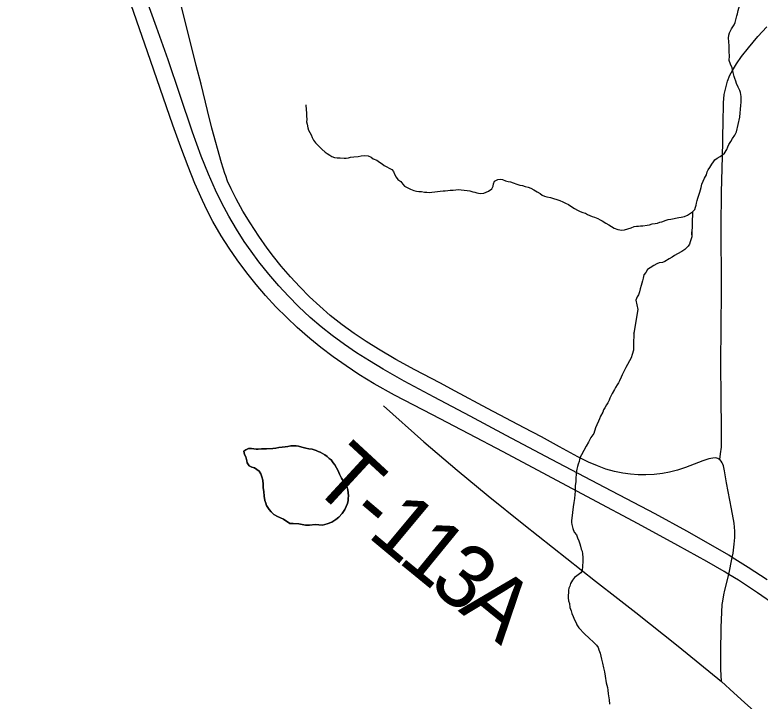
# Model space of a CAD drawing. Extents: x -17 to 88, y -5 to 22.
# Drawn here: x -15.624 to -14.955, y 18.189 to 18.805 of the extents above; entities that cross this region are included whole.
import ezdxf

# ---------------------------------------------------------------- set-up
doc = ezdxf.new("R2010")
doc.units = 0
for name, color, linetype in [('GM_X_County_Road', 7, 'Continuous'), ('GM_X_Minor_Lake', 7, 'Continuous'), ('GM_X_Minor_River', 7, 'Continuous'), ('GM_X_Township_Road', 7, 'Continuous'), ('GM_X_Township_Road_Text', 7, 'Continuous'), ('GM_X_US_Route', 7, 'Continuous')]:
    doc.layers.add(name, color=color, linetype=linetype)

msp = doc.modelspace()

# ---------------------------------------------------------------- linework, layer by layer
at = {"layer": 'GM_X_County_Road'}
for points in [[(-15.43442, 18.66023), (-15.4352, 18.66242), (-15.43811, 18.67197), (-15.44685, 18.7031), (-15.4508, 18.7188), (-15.45633, 18.74239), (-15.46084, 18.75918), (-15.47433, 18.81346), (-15.48111, 18.83865), (-15.48462, 18.85054), (-15.49156, 18.87179), (-15.5076, 18.91951), (-15.5232, 18.9654), (-15.53738, 19.00653), (-15.56505, 19.08573), (-15.5758, 19.11553), (-15.60344, 19.18946), (-15.62132, 19.23584), (-15.6236, 19.24164)], [(-14.99098, 18.40567), (-14.99178, 18.40623), (-14.99268, 18.40666), (-14.99358, 18.40695), (-14.99513, 18.40717), (-14.99738, 18.40713), (-15.00085, 18.40636), (-15.00609, 18.4045), (-15.02183, 18.39852), (-15.02898, 18.39621), (-15.03626, 18.39433), (-15.04243, 18.39321), (-15.04991, 18.3924), (-15.05741, 18.39202), (-15.06429, 18.3921), (-15.07116, 18.39261), (-15.07799, 18.39357), (-15.08535, 18.39508), (-15.0932, 18.39725), (-15.10086, 18.40002), (-15.10887, 18.40356), (-15.11837, 18.40828), (-15.13478, 18.41718), (-15.15112, 18.42614), (-15.16651, 18.43423), (-15.19958, 18.45149), (-15.22856, 18.46716), (-15.24221, 18.47453), (-15.26481, 18.4863), (-15.2817, 18.49561), (-15.29726, 18.50475), (-15.30836, 18.51166), (-15.31923, 18.51893), (-15.32984, 18.52657), (-15.34056, 18.53512), (-15.35, 18.54326), (-15.35911, 18.55176), (-15.3679, 18.56059), (-15.37638, 18.56972), (-15.38456, 18.57912), (-15.39165, 18.58781), (-15.39729, 18.59528), (-15.40471, 18.60605), (-15.41251, 18.61806), (-15.41901, 18.6287), (-15.42513, 18.63956), (-15.42964, 18.64847), (-15.43266, 18.65535), (-15.43442, 18.66023)], [(-14.97983, 18.31801), (-14.97911, 18.32186), (-14.97798, 18.32981), (-14.97754, 18.33593), (-14.9775, 18.34143), (-14.97822, 18.34876), (-14.98053, 18.36155), (-14.98497, 18.38477), (-14.9862, 18.39214), (-14.98681, 18.39578), (-14.98766, 18.39999), (-14.98817, 18.4016), (-14.98871, 18.40279), (-14.98979, 18.40443), (-14.99098, 18.40567)], [(-14.98287, 18.30274), (-14.97983, 18.31801)], [(-14.9894, 18.20667), (-14.99004, 18.21775), (-14.98992, 18.23268), (-14.98961, 18.25505), (-14.98928, 18.26876), (-14.98874, 18.27563), (-14.98835, 18.27874), (-14.98742, 18.2843), (-14.98648, 18.28858), (-14.98287, 18.30274)], [(-14.72434, 17.87666), (-14.7323, 17.88854), (-14.75121, 17.91776), (-14.76907, 17.94467), (-14.78233, 17.96421), (-14.79562, 17.98374), (-14.81879, 18.01757), (-14.83863, 18.04615), (-14.85954, 18.07548), (-14.86774, 18.0864), (-14.87667, 18.09752), (-14.88598, 18.10832), (-14.89776, 18.12109), (-14.90769, 18.13133), (-14.92012, 18.14348), (-14.93733, 18.15962), (-14.9687, 18.18793), (-14.97842, 18.19663), (-14.9894, 18.20667)]]:
    msp.add_lwpolyline(points, dxfattribs=at)
at = {"layer": 'GM_X_Minor_Lake'}
for points in [[(-15.32407, 18.37319), (-15.32483, 18.37851), (-15.32558, 18.38155), (-15.32672, 18.38421), (-15.32862, 18.3861), (-15.33052, 18.38914), (-15.33242, 18.39256), (-15.33356, 18.3956), (-15.33508, 18.39825), (-15.33659, 18.40091), (-15.33811, 18.40281), (-15.33963, 18.40547), (-15.34153, 18.40661), (-15.34343, 18.40851), (-15.34532, 18.41002), (-15.3476, 18.41116), (-15.3495, 18.4123), (-15.3514, 18.41306), (-15.35329, 18.41382), (-15.35671, 18.41496), (-15.35974, 18.41534), (-15.3624, 18.4161), (-15.36619, 18.41686), (-15.36923, 18.41762), (-15.37113, 18.418), (-15.3734, 18.418), (-15.37606, 18.418), (-15.37872, 18.41761), (-15.38099, 18.41723), (-15.38365, 18.41685), (-15.38668, 18.41647), (-15.38934, 18.4161), (-15.392, 18.41571), (-15.39769, 18.41533), (-15.40224, 18.41533), (-15.40527, 18.41495), (-15.40717, 18.41495), (-15.40907, 18.41533), (-15.41135, 18.41571), (-15.414, 18.41571), (-15.41628, 18.41457), (-15.41818, 18.41343)], [(-15.41818, 18.41343), (-15.41628, 18.41457), (-15.414, 18.41571), (-15.41135, 18.41571), (-15.40907, 18.41533), (-15.40717, 18.41495), (-15.40527, 18.41495), (-15.40224, 18.41533), (-15.39769, 18.41533), (-15.392, 18.41571), (-15.38934, 18.4161), (-15.38668, 18.41647), (-15.38365, 18.41685), (-15.38099, 18.41723), (-15.37872, 18.41761), (-15.37606, 18.418), (-15.3734, 18.418), (-15.37113, 18.418), (-15.36923, 18.41762), (-15.36619, 18.41686), (-15.3624, 18.4161), (-15.35974, 18.41534), (-15.35671, 18.41496), (-15.35329, 18.41382), (-15.3514, 18.41306), (-15.3495, 18.4123), (-15.3476, 18.41116), (-15.34532, 18.41002), (-15.34343, 18.40851), (-15.34153, 18.40661), (-15.33963, 18.40547), (-15.33811, 18.40281), (-15.33659, 18.40091), (-15.33508, 18.39825), (-15.33356, 18.3956), (-15.33242, 18.39256), (-15.33052, 18.38914), (-15.32862, 18.3861), (-15.32672, 18.38421), (-15.32558, 18.38155), (-15.32483, 18.37851), (-15.32407, 18.37319), (-15.32444, 18.37091), (-15.32444, 18.36902), (-15.3252, 18.36636), (-15.32634, 18.3637), (-15.32748, 18.36104), (-15.32975, 18.35725), (-15.33279, 18.35421), (-15.33544, 18.35193), (-15.33924, 18.34965), (-15.34341, 18.34813), (-15.34758, 18.34699), (-15.35403, 18.34737), (-15.35934, 18.34699), (-15.36276, 18.34699), (-15.36883, 18.34813), (-15.37376, 18.3485), (-15.3768, 18.3485), (-15.38249, 18.3523), (-15.3878, 18.35458), (-15.39122, 18.35648), (-15.3935, 18.35875), (-15.3954, 18.36103), (-15.39767, 18.36445), (-15.39843, 18.36673), (-15.39919, 18.369), (-15.39995, 18.3728), (-15.40033, 18.37698), (-15.40071, 18.3804), (-15.40071, 18.38343), (-15.40109, 18.38723), (-15.40185, 18.39027), (-15.40299, 18.39293), (-15.40451, 18.39521), (-15.40869, 18.39824), (-15.41096, 18.399), (-15.41324, 18.40014), (-15.41514, 18.4028), (-15.41552, 18.4047), (-15.41628, 18.40812), (-15.41742, 18.41039), (-15.41818, 18.41343)], [(-15.41818, 18.41343), (-15.41742, 18.41039), (-15.41628, 18.40812), (-15.41552, 18.4047), (-15.41514, 18.4028), (-15.41324, 18.40014), (-15.41096, 18.399), (-15.40869, 18.39824), (-15.40451, 18.39521), (-15.40299, 18.39293), (-15.40185, 18.39027), (-15.40109, 18.38723), (-15.40071, 18.38343), (-15.40071, 18.3804), (-15.40033, 18.37698), (-15.39995, 18.3728), (-15.39919, 18.369), (-15.39843, 18.36673), (-15.39767, 18.36445), (-15.3954, 18.36103), (-15.3935, 18.35875), (-15.39122, 18.35648), (-15.3878, 18.35458), (-15.38249, 18.3523), (-15.3768, 18.3485), (-15.37376, 18.3485), (-15.36883, 18.34813), (-15.36276, 18.34699), (-15.35934, 18.34699), (-15.35403, 18.34737), (-15.34758, 18.34699), (-15.34341, 18.34813), (-15.33924, 18.34965), (-15.33544, 18.35193), (-15.33279, 18.35421), (-15.32975, 18.35725), (-15.32748, 18.36104), (-15.32634, 18.3637), (-15.3252, 18.36636), (-15.32444, 18.36902), (-15.32444, 18.37091), (-15.32407, 18.37319)]]:
    msp.add_lwpolyline(points, dxfattribs=at)
at = {"layer": 'GM_X_Minor_River'}
for points in [[(-14.9828, 18.78637), (-14.98238, 18.78864), (-14.98041, 18.79203), (-14.97924, 18.7939), (-14.97806, 18.79578), (-14.97727, 18.79767), (-14.97644, 18.80145), (-14.97563, 18.80371), (-14.97522, 18.8056), (-14.9744, 18.80862), (-14.97399, 18.81051), (-14.97319, 18.8124), (-14.97239, 18.81466), (-14.9712, 18.8173), (-14.97038, 18.82032), (-14.96958, 18.82258), (-14.96878, 18.82485), (-14.96132, 18.83762)], [(-15.1346, 18.63806), (-15.13196, 18.63688), (-15.12932, 18.63569), (-15.12668, 18.6345), (-15.12367, 18.63254), (-15.12142, 18.63098), (-15.11879, 18.62941), (-15.11615, 18.62823), (-15.11388, 18.62742), (-15.11162, 18.62662), (-15.10974, 18.62545), (-15.10747, 18.62465), (-15.10559, 18.62385), (-15.10332, 18.62305), (-15.1003, 18.62186), (-15.09842, 18.62068), (-15.09654, 18.61989), (-15.09315, 18.61792), (-15.09052, 18.61636), (-15.08827, 18.6148), (-15.08564, 18.61323), (-15.08262, 18.61203), (-15.07882, 18.61158), (-15.07654, 18.61192), (-15.07348, 18.61262), (-15.07042, 18.61371), (-15.06774, 18.61479), (-15.06583, 18.61514), (-15.06393, 18.6151), (-15.06202, 18.61545), (-15.06012, 18.61541), (-15.05631, 18.6161), (-15.05402, 18.61644), (-15.05173, 18.61715), (-15.04906, 18.61748), (-15.04677, 18.61782), (-15.04486, 18.61855), (-15.04295, 18.61889), (-15.03912, 18.62034), (-15.03721, 18.62106), (-15.03492, 18.6214), (-15.02767, 18.62278), (-15.02576, 18.62313), (-15.02271, 18.62383), (-15.02003, 18.62492), (-15.01811, 18.62602), (-15.01541, 18.62787), (-15.01347, 18.63011), (-15.01267, 18.632), (-15.01226, 18.63389), (-15.01184, 18.63578), (-15.01142, 18.63805), (-15.01061, 18.64031), (-15.0098, 18.64296), (-15.009, 18.6456), (-15.00778, 18.64975), (-15.00696, 18.65278), (-15.00577, 18.65541), (-15.00458, 18.65805), (-15.00301, 18.66106), (-15.0022, 18.6637), (-15.0014, 18.66558), (-14.99984, 18.66783), (-14.99826, 18.67084), (-14.9967, 18.67271), (-14.99553, 18.67459), (-14.99322, 18.67607), (-14.99053, 18.67753), (-14.9886, 18.67902), (-14.98668, 18.6805), (-14.98471, 18.68388), (-14.98391, 18.68614), (-14.98273, 18.6884), (-14.98116, 18.69103), (-14.97959, 18.69366), (-14.97763, 18.69666), (-14.97605, 18.69967), (-14.97314, 18.71291), (-14.97269, 18.71669), (-14.97226, 18.71972), (-14.97219, 18.72352), (-14.97176, 18.72617), (-14.97172, 18.72845), (-14.97166, 18.73149), (-14.97236, 18.73492), (-14.97308, 18.73683), (-14.97454, 18.73989), (-14.97601, 18.74296), (-14.97672, 18.74525), (-14.97744, 18.74754), (-14.97816, 18.74945), (-14.97886, 18.75289), (-14.97993, 18.75708), (-14.98138, 18.76053), (-14.98246, 18.76358), (-14.98239, 18.76776), (-14.98269, 18.77156), (-14.9826, 18.7765), (-14.98291, 18.78068), (-14.98323, 18.78373), (-14.9828, 18.78637)], [(-15.36262, 18.72395), (-15.36233, 18.71939), (-15.362, 18.71672), (-15.36204, 18.71406), (-15.36173, 18.71064), (-15.36176, 18.70874), (-15.36143, 18.70646), (-15.36072, 18.70341), (-15.36001, 18.70112), (-15.3589, 18.6992), (-15.3578, 18.6969), (-15.35671, 18.6946), (-15.35561, 18.6923), (-15.35375, 18.68999), (-15.35114, 18.68728), (-15.34815, 18.68419), (-15.34516, 18.68147), (-15.34329, 18.6803), (-15.34103, 18.67874), (-15.33915, 18.67756), (-15.33689, 18.67676), (-15.33423, 18.67633), (-15.33158, 18.67628), (-15.32815, 18.67622), (-15.32625, 18.67618), (-15.32435, 18.67653), (-15.32244, 18.67687), (-15.31939, 18.6772), (-15.31558, 18.67751), (-15.31291, 18.67821), (-15.31024, 18.67854), (-15.30645, 18.6781), (-15.30381, 18.67691), (-15.30194, 18.67535), (-15.29892, 18.67416), (-15.29629, 18.67259), (-15.29403, 18.67103), (-15.29216, 18.66947), (-15.2899, 18.66829), (-15.28765, 18.66711), (-15.28539, 18.66593), (-15.2839, 18.664), (-15.2828, 18.66171), (-15.28133, 18.65902), (-15.27985, 18.65709), (-15.27722, 18.65515), (-15.27536, 18.65283), (-15.27388, 18.65091), (-15.27162, 18.64973), (-15.26861, 18.64815), (-15.26559, 18.64696), (-15.26332, 18.64653), (-15.26104, 18.64611), (-15.25876, 18.64607), (-15.25611, 18.64564), (-15.25383, 18.6456), (-15.25194, 18.64518), (-15.24927, 18.64551), (-15.2466, 18.64584), (-15.24432, 18.64618), (-15.24203, 18.64652), (-15.23936, 18.64685), (-15.23746, 18.64681), (-15.23517, 18.64715), (-15.23288, 18.64749), (-15.23022, 18.64744), (-15.22794, 18.64778), (-15.22565, 18.64811), (-15.21768, 18.6472), (-15.21541, 18.64678), (-15.21276, 18.64597), (-15.21087, 18.64556), (-15.20898, 18.64514), (-15.20595, 18.64433), (-15.2029, 18.64465), (-15.19869, 18.64647), (-15.19561, 18.64869), (-15.19442, 18.65095), (-15.194, 18.65322), (-15.1932, 18.65548), (-15.19013, 18.65694), (-15.18822, 18.65729), (-15.18595, 18.65687), (-15.18331, 18.65568), (-15.18104, 18.65525), (-15.17876, 18.65483), (-15.1765, 18.65403), (-15.1731, 18.65283), (-15.17045, 18.65202), (-15.16818, 18.6516), (-15.16553, 18.65079), (-15.16289, 18.64998), (-15.16062, 18.64918), (-15.15799, 18.64761), (-15.15498, 18.64604), (-15.15234, 18.64447), (-15.15047, 18.64292), (-15.14821, 18.64211), (-15.14632, 18.64132), (-15.14291, 18.64088), (-15.1346, 18.63806)], [(-15.01541, 18.62787), (-15.01617, 18.60738), (-15.01612, 18.61004), (-15.01617, 18.60738), (-15.01621, 18.60548), (-15.01743, 18.60095), (-15.01823, 18.59906), (-15.0194, 18.59719), (-15.0225, 18.59421), (-15.0252, 18.59236), (-15.02904, 18.59015), (-15.03173, 18.58868), (-15.03366, 18.5872), (-15.03634, 18.58573), (-15.04019, 18.58352), (-15.04249, 18.58243), (-15.04554, 18.5821), (-15.04745, 18.58138), (-15.05014, 18.57991), (-15.0536, 18.5777), (-15.05591, 18.57622), (-15.05748, 18.57359), (-15.05904, 18.57134), (-15.05986, 18.56832), (-15.06028, 18.56605), (-15.0615, 18.56189), (-15.06232, 18.55887), (-15.06313, 18.55623), (-15.06394, 18.55359), (-15.06511, 18.55171), (-15.06631, 18.54869), (-15.0644, 18.54046)], [(-15.0644, 18.54046), (-15.06799, 18.51904), (-15.06799, 18.51943), (-15.06799, 18.51715), (-15.06799, 18.51525), (-15.06836, 18.51297), (-15.06836, 18.51107), (-15.06836, 18.50879), (-15.06836, 18.50689), (-15.06836, 18.50386), (-15.0695, 18.50006), (-15.07064, 18.49702), (-15.07215, 18.49436), (-15.07367, 18.49095), (-15.07519, 18.48829), (-15.0786, 18.48183), (-15.07936, 18.47955), (-15.08088, 18.47651), (-15.08201, 18.47461), (-15.08315, 18.47272), (-15.08467, 18.47044), (-15.08543, 18.46854), (-15.0877, 18.46512), (-15.08846, 18.46322), (-15.0896, 18.46094), (-15.09036, 18.45905), (-15.09149, 18.45677), (-15.09263, 18.45487), (-15.09415, 18.45221), (-15.09529, 18.45031), (-15.09605, 18.44841), (-15.09794, 18.44461), (-15.09908, 18.44234), (-15.09984, 18.44006), (-15.10136, 18.43702), (-15.10249, 18.43436), (-15.10401, 18.42904), (-15.10666, 18.42563), (-15.10894, 18.42145), (-15.11084, 18.41765), (-15.11311, 18.41385), (-15.11501, 18.41006), (-15.11615, 18.40778), (-15.1169, 18.40588), (-15.11728, 18.40398), (-15.11804, 18.4017), (-15.1188, 18.39942), (-15.11918, 18.39714), (-15.11994, 18.39373), (-15.11994, 18.39183), (-15.12031, 18.38993), (-15.12031, 18.38765), (-15.12031, 18.38575), (-15.12069, 18.38234), (-15.12069, 18.38044), (-15.12069, 18.3774), (-15.12107, 18.37436), (-15.12145, 18.37094), (-15.12183, 18.36714), (-15.12258, 18.36335), (-15.12372, 18.3531), (-15.1241, 18.3512), (-15.1241, 18.3493), (-15.12372, 18.3474), (-15.12296, 18.34398), (-15.12182, 18.34056), (-15.11954, 18.33828), (-15.11878, 18.33563), (-15.11764, 18.33297), (-15.1165, 18.33031), (-15.11612, 18.32803), (-15.11536, 18.32538), (-15.1146, 18.32348), (-15.11422, 18.3212), (-15.11384, 18.31778), (-15.11384, 18.31436), (-15.11422, 18.31019), (-15.1146, 18.30601), (-15.11574, 18.30411), (-15.11915, 18.30145), (-15.12143, 18.29993), (-15.12332, 18.29765), (-15.12484, 18.29461), (-15.1256, 18.29234), (-15.12636, 18.29044), (-15.12674, 18.28854), (-15.12674, 18.28626), (-15.12711, 18.28398), (-15.12711, 18.2817), (-15.12673, 18.27905), (-15.12597, 18.27677), (-15.12559, 18.27297), (-15.12445, 18.26993), (-15.1237, 18.26766), (-15.12256, 18.265), (-15.12142, 18.26196), (-15.1199, 18.2593), (-15.11914, 18.2574), (-15.11762, 18.25475), (-15.11231, 18.24943), (-15.10813, 18.24563)], [(-15.0652, 18.54286), (-15.0652, 18.54286)], [(-15.10813, 18.24563), (-15.10434, 18.24184), (-15.10168, 18.23918), (-15.10016, 18.23728), (-15.0994, 18.235), (-15.09826, 18.23196), (-15.09788, 18.22931), (-15.09712, 18.22665), (-15.09636, 18.22323), (-15.09522, 18.21905), (-15.09447, 18.21525), (-15.09371, 18.21146), (-15.09294, 18.20538), (-15.0918, 18.20121), (-15.09143, 18.19893), (-15.09104, 18.19551), (-15.09028, 18.19019), (-15.0899, 18.1864)]]:
    msp.add_lwpolyline(points, dxfattribs=at)
at = {"layer": 'GM_X_Township_Road'}
for points in [[(-14.99098, 18.40567), (-14.99022, 18.41086), (-14.98932, 18.41693), (-14.9895, 18.43507), (-14.98963, 18.4593), (-14.99, 18.49347), (-14.98971, 18.52331), (-14.98956, 18.55811), (-14.98943, 18.57612), (-14.9897, 18.5997), (-14.98974, 18.61455), (-14.98933, 18.64547), (-14.98858, 18.67762), (-14.98823, 18.69119), (-14.98815, 18.69674), (-14.98795, 18.70719), (-14.98754, 18.72567), (-14.98692, 18.73309), (-14.98571, 18.7392), (-14.98394, 18.74518), (-14.98188, 18.7504), (-14.97961, 18.75487), (-14.97602, 18.76069), (-14.9714, 18.76732), (-14.96528, 18.77518), (-14.95682, 18.78515), (-14.94886, 18.79391)], [(-15.29286, 18.45381), (-15.25662, 18.42155), (-15.2268, 18.39617), (-15.19898, 18.37323), (-15.16695, 18.34759), (-15.10254, 18.29676), (-15.08238, 18.28117), (-15.06621, 18.26857), (-15.02822, 18.23847), (-14.9894, 18.20667)]]:
    msp.add_lwpolyline(points, dxfattribs=at)
at = {"layer": 'GM_X_US_Route'}
for points in [[(-14.9407, 18.27475), (-14.95704, 18.28614), (-14.97418, 18.29744), (-14.98287, 18.30274), (-14.98694, 18.30522), (-15.00255, 18.31426), (-15.02861, 18.32881), (-15.0641, 18.34814), (-15.10583, 18.37028), (-15.1854, 18.4126), (-15.21617, 18.42886), (-15.24869, 18.4458), (-15.28283, 18.46361), (-15.30131, 18.47378), (-15.31506, 18.48216), (-15.32644, 18.48968), (-15.33807, 18.49792), (-15.34891, 18.50619), (-15.35899, 18.51443), (-15.37018, 18.52423), (-15.37969, 18.53313), (-15.38932, 18.54279), (-15.39858, 18.55279), (-15.40707, 18.56266), (-15.41559, 18.5733), (-15.42409, 18.58476), (-15.43145, 18.5955), (-15.43842, 18.60648), (-15.44589, 18.61934), (-15.45103, 18.62923), (-15.45537, 18.63815), (-15.46207, 18.6535), (-15.46809, 18.66848), (-15.47475, 18.68588), (-15.48197, 18.70572), (-15.50471, 18.77151), (-15.56533, 18.94651)], [(-14.94832, 18.29788), (-14.96548, 18.30908), (-14.97983, 18.31801), (-14.98288, 18.3199), (-14.9989, 18.3294), (-15.02053, 18.34162), (-15.04891, 18.35705), (-15.09403, 18.38073), (-15.14196, 18.40577), (-15.18256, 18.42739), (-15.21494, 18.4446), (-15.24734, 18.46176), (-15.27415, 18.47622), (-15.29313, 18.48689), (-15.30544, 18.49419), (-15.317, 18.50153), (-15.32781, 18.5089), (-15.33886, 18.51701), (-15.34862, 18.52475), (-15.35855, 18.53327), (-15.369, 18.54307), (-15.37817, 18.55241), (-15.38663, 18.56156), (-15.39562, 18.57191), (-15.40461, 18.58306), (-15.41168, 18.59256), (-15.41771, 18.60128), (-15.42475, 18.61231), (-15.43164, 18.62417), (-15.43781, 18.63571), (-15.44356, 18.64746), (-15.44995, 18.66166), (-15.45648, 18.67783), (-15.46428, 18.6995), (-15.47562, 18.73307), (-15.48615, 18.76428), (-15.49652, 18.79356), (-15.51287, 18.83921)]]:
    msp.add_lwpolyline(points, dxfattribs=at)

# ---------------------------------------------------------------- texts
at = {"layer": 'GM_X_Township_Road_Text'}
for s, rotation, p in [('T', 317.31581, (-15.35966, 18.38334)), ('-', 319.74302, (-15.32645, 18.35279)), ('1', 320.16991, (-15.30828, 18.33741)), ('1', 320.76406, (-15.28091, 18.31459)), ('3', 320.94753, (-15.25365, 18.29232)), ('A', 321.0083, (-15.22642, 18.27023))]:
    msp.add_text(s, height=0.05682, rotation=rotation, dxfattribs=at).set_placement(p)

doc.saveas('drawing.dxf')
